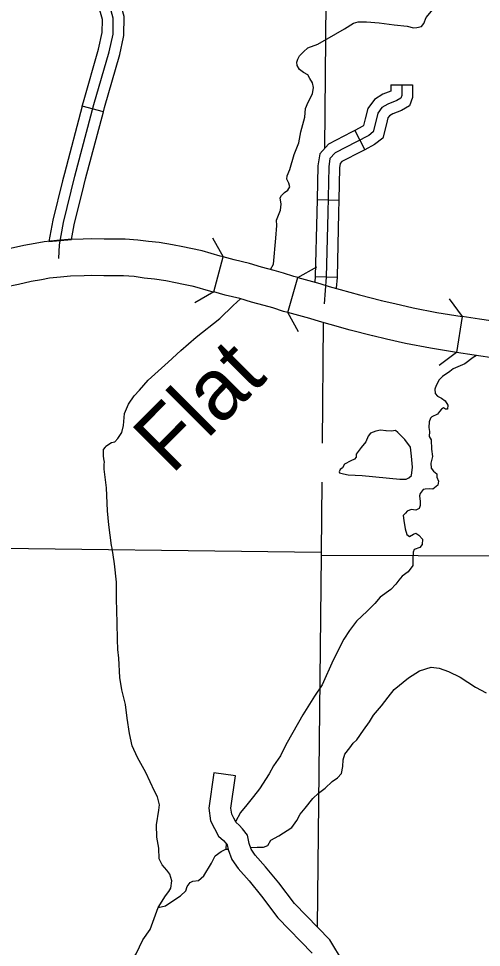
# Model space of a CAD drawing. Extents: x 813775 to 1157140, y 1757555 to 1979907.
# Drawn here: x 919245 to 925607, y 1817730 to 1830487 of the extents above; entities that cross this region are included whole.
import ezdxf

# ---------------------------------------------------------------- set-up
doc = ezdxf.new("R2010")
doc.units = 0
for name, color, linetype in [('Level 10', 7, 'Continuous'), ('Level 31', 7, 'Continuous'), ('Level 32', 7, 'Continuous'), ('Level 35', 7, 'Continuous'), ('Level 37', 7, 'Continuous'), ('Level 4', 7, 'Continuous'), ('Level 46', 7, 'Continuous'), ('Level 5', 7, 'Continuous')]:
    doc.layers.add(name, color=color, linetype=linetype)

msp = doc.modelspace()

# ---------------------------------------------------------------- linework, layer by layer
at = {"layer": 'Level 10'}
msp.add_line((922059, 1827214), (922059, 1827214), dxfattribs=at)
for points in [[(920131, 1827459), (919927, 1827452), (919773, 1827439), (919596, 1827420), (919472, 1827397), (919319, 1827371), (919136, 1827329), (918950, 1827290), (918743, 1827234), (918576, 1827192), (918447, 1827154), (918241, 1827102), (918071, 1827055)], [(921769, 1827296), (921614, 1827331), (921502, 1827353), (921360, 1827381), (921178, 1827411), (921029, 1827425), (920884, 1827444), (920710, 1827456), (920546, 1827459), (920420, 1827459), (920252, 1827462), (920133, 1827459)], [(922059, 1827214), (922017, 1827225), (921769, 1827296)], [(921928, 1826732), (922059, 1827214)], [(923026, 1826944), (922887, 1826990), (922757, 1827028), (922585, 1827074), (922417, 1827125), (922206, 1827175), (922059, 1827214)], [(918205, 1826573), (918369, 1826619), (918579, 1826671), (918708, 1826710), (918869, 1826750), (919067, 1826804), (919244, 1826841), (919416, 1826881), (919559, 1826905), (919668, 1826925), (919821, 1826941), (919957, 1826953), (920147, 1826959)], [(920145, 1826959), (920254, 1826962), (920415, 1826959), (920541, 1826959), (920689, 1826957), (920833, 1826947), (920972, 1826928), (921114, 1826914), (921271, 1826889), (921404, 1826863), (921511, 1826841), (921647, 1826811)], [(922946, 1826448), (923081, 1826929)], [(923081, 1826929), (923026, 1826944)], [(923081, 1826929), (923384, 1826847), (923516, 1826808), (923663, 1826768), (923931, 1826692), (924234, 1826614)], [(921632, 1826815), (921883, 1826743), (921928, 1826732)], [(922888, 1826464), (922739, 1826513), (922622, 1826546), (922448, 1826593), (922288, 1826641), (922083, 1826690), (921928, 1826732)], [(924229, 1826615), (924415, 1826572), (924667, 1826512), (924993, 1826451), (925340, 1826395)], [(922946, 1826448), (922888, 1826464)], [(924110, 1826130), (923801, 1826209), (923528, 1826286), (923379, 1826327), (923248, 1826366), (922946, 1826448)], [(925340, 1826395), (925266, 1825900)], [(926379, 1826241), (926083, 1826279), (925893, 1826312), (925581, 1826359), (925340, 1826395)], [(925266, 1825900), (924906, 1825959), (924564, 1826023), (924301, 1826085), (924115, 1826129)], [(926314, 1825745), (926009, 1825785), (925814, 1825818), (925507, 1825864), (925266, 1825900)]]:
    msp.add_lwpolyline(points, dxfattribs=at)
at = {"layer": 'Level 31'}
for p in [(920410, 1829207), (920120, 1829284)]:
    msp.add_line(p, (920120, 1829284), dxfattribs=at)
for points in [[(920393, 1830289), (920397, 1830474), (920331, 1830711), (920253, 1831083), (920229, 1831281), (920229, 1831294)], [(920688, 1830232), (920693, 1830253), (920698, 1830513), (920622, 1830783), (920549, 1831131), (920528, 1831306), (920528, 1831307)], [(920120, 1829284), (920136, 1829345), (920344, 1830068), (920395, 1830297)], [(920410, 1829207), (920426, 1829265), (920635, 1829994), (920688, 1830232)], [(920120, 1829284), (919874, 1828360), (919849, 1828260)], [(920141, 1828189), (920164, 1828286), (920410, 1829207)], [(919849, 1828260), (919717, 1827719), (919662, 1827427), (919972, 1827454)], [(919972, 1827454), (920010, 1827656), (920141, 1828189)]]:
    msp.add_lwpolyline(points, dxfattribs=at)
at = {"layer": 'Level 32'}
for p, q in [((924361, 1829579), (924661, 1829579)), ((923865, 1828951), (924005, 1828685)), ((923348, 1828000), (923648, 1827993)), ((923322, 1826945), (923622, 1826937))]:
    msp.add_line(p, q, dxfattribs=at)
for points in [[(919797, 1827190), (919806, 1827381), (919864, 1827688), (920019, 1828323), (920281, 1829305), (920490, 1830031), (920543, 1830271), (920547, 1830494), (920476, 1830747), (920401, 1831107), (920379, 1831294), (920370, 1831498), (920374, 1831694), (920454, 1832023), (920627, 1832397), (920938, 1832948), (921093, 1833299), (921187, 1833605), (921240, 1834010)], [(924361, 1829579), (924361, 1829490), (924253, 1829448), (924138, 1829377), (924044, 1829254), (924010, 1829109), (923987, 1829018), (923977, 1829010), (923865, 1828951)], [(924661, 1829579), (924661, 1829401), (924619, 1829290), (924510, 1829226), (924387, 1829178), (924342, 1829151), (924321, 1829123), (924302, 1829039), (924253, 1828843), (924139, 1828756), (924005, 1828685)], [(924511, 1829579), (924511, 1829428), (924498, 1829393), (924444, 1829362), (924320, 1829313), (924240, 1829264), (924182, 1829188)], [(924182, 1829188), (924156, 1829074), (924120, 1828931), (924058, 1828883), (923889, 1828794), (923596, 1828643), (923525, 1828563), (923508, 1828452), (923494, 1827821), (923472, 1826936), (923447, 1826568)], [(923865, 1828951), (923820, 1828927), (923503, 1828764), (923384, 1828630), (923358, 1828465), (923348, 1828000)], [(924005, 1828685), (923959, 1828661), (923690, 1828523), (923666, 1828496), (923657, 1828438), (923648, 1827993)], [(923348, 1828000), (923344, 1827824), (923322, 1826945)], [(923648, 1827993), (923644, 1827817), (923622, 1826937)], [(923322, 1826945), (923322, 1826943), (923317, 1826865)], [(923622, 1826937), (923622, 1826930), (923612, 1826782)]]:
    msp.add_lwpolyline(points, dxfattribs=at)
at = {"layer": 'Level 35'}
for points in [[(924200, 1830427), (924408, 1830401), (924585, 1830381), (924675, 1830358), (924721, 1830363), (924781, 1830376), (924817, 1830421), (924849, 1830502), (924922, 1830588), (925011, 1830686), (925053, 1830797), (925167, 1830908), (925293, 1830976), (925338, 1831042), (925366, 1831072), (925404, 1831085), (925447, 1831100), (925474, 1831135), (925484, 1831186), (925469, 1831213), (925457, 1831236), (925457, 1831266)], [(923224, 1829338), (923287, 1829451), (923297, 1829539), (923285, 1829605), (923249, 1829663), (923219, 1829713), (923161, 1829746), (923108, 1829789), (923075, 1829844), (923070, 1829890), (923081, 1829930), (923108, 1829973), (923159, 1830029), (923222, 1830084), (923358, 1830137), (923605, 1830276), (923723, 1830346), (923847, 1830425), (923912, 1830440), (924028, 1830442), (924200, 1830427)], [(922975, 1828414), (923033, 1828622), (923098, 1828778), (923126, 1828930), (923179, 1829134), (923189, 1829250), (923224, 1829338)], [(922707, 1827041), (922748, 1827115), (922779, 1827471), (922794, 1827647), (922789, 1827720), (922844, 1827854), (922854, 1827937), (922842, 1828023), (922859, 1828056), (922900, 1828096), (922945, 1828129), (922973, 1828175), (922960, 1828225), (922932, 1828280), (922935, 1828326), (922975, 1828414)], [(921027, 1825519), (921301, 1825769), (921475, 1825928), (921687, 1826110), (922010, 1826367), (922194, 1826547), (922295, 1826639)], [(925541, 1825859), (925494, 1825830), (925377, 1825743), (925217, 1825678), (925173, 1825640)], [(925173, 1825640), (925071, 1825571), (925028, 1825526)], [(920445, 1824616), (920521, 1824666), (920566, 1824676), (920609, 1824719), (920664, 1824800), (920687, 1824898), (920702, 1825062), (920755, 1825189), (920833, 1825305), (920909, 1825383), (921027, 1825519)], [(925028, 1825526), (924986, 1825448), (924965, 1825396), (924970, 1825339), (925003, 1825303), (925060, 1825274), (925109, 1825235), (925147, 1825176), (925139, 1825121), (925114, 1825121), (925084, 1825140), (925057, 1825124), (925030, 1825089), (925005, 1825053), (924924, 1825015), (924905, 1824999), (924889, 1824947), (924886, 1824871), (924894, 1824814), (924889, 1824749), (924916, 1824700), (924921, 1824572), (924932, 1824471), (924913, 1824379), (924916, 1824311), (924948, 1824270), (924992, 1824234), (924995, 1824188), (925016, 1824134), (925008, 1824079), (924940, 1824025), (924889, 1824030), (924834, 1824025), (924804, 1824020), (924766, 1823965), (924755, 1823930), (924766, 1823854), (924764, 1823799), (924750, 1823758), (924707, 1823737), (924639, 1823745), (924584, 1823720), (924563, 1823696), (924533, 1823663), (924541, 1823594)], [(924299, 1824827), (924220, 1824835), (924155, 1824821), (924084, 1824794), (924049, 1824750), (924016, 1824672), (923956, 1824595), (923886, 1824506), (923886, 1824465), (923861, 1824435), (923810, 1824413), (923725, 1824367), (923698, 1824315), (923663, 1824296), (923652, 1824263), (923658, 1824247), (923712, 1824236), (923774, 1824220), (923967, 1824212), (924484, 1824163), (924573, 1824163), (924611, 1824179), (924647, 1824212), (924658, 1824326), (924647, 1824476), (924630, 1824601), (924554, 1824704), (924457, 1824802), (924424, 1824829), (924372, 1824821), (924291, 1824827)], [(920523, 1823251), (920485, 1823535), (920468, 1823726), (920453, 1824042), (920420, 1824297), (920420, 1824365), (920425, 1824395), (920417, 1824440), (920412, 1824483), (920412, 1824526), (920412, 1824567), (920442, 1824602), (920445, 1824616)], [(924541, 1823594), (924557, 1823480)], [(924557, 1823480), (924582, 1823402), (924617, 1823374), (924671, 1823404), (924704, 1823418), (924747, 1823391), (924796, 1823336), (924793, 1823265), (924761, 1823222), (924682, 1823195), (924668, 1823157), (924663, 1823075), (924663, 1822974), (924601, 1822887), (924519, 1822828), (924470, 1822776), (924429, 1822721), (924361, 1822645), (924217, 1822539), (924141, 1822452), (924035, 1822349), (923888, 1822213), (923793, 1822082), (923717, 1821963)], [(920606, 1821959), (920601, 1822189), (920589, 1822517), (920591, 1822746), (920563, 1822996), (920533, 1823213), (920523, 1823251)], [(920768, 1820668), (920737, 1820877), (920715, 1821068), (920662, 1821270), (920639, 1821437), (920624, 1821702), (920611, 1821820), (920606, 1821959)], [(923717, 1821963), (923571, 1821674), (923416, 1821336), (923313, 1821181), (923150, 1820926), (923014, 1820681)], [(922435, 1819101), (922525, 1819106), (922612, 1819106), (922669, 1819131), (922710, 1819201), (922824, 1819264), (923001, 1819378), (923071, 1819473), (923115, 1819558), (923183, 1819642), (923289, 1819775), (923368, 1819849), (923460, 1819917), (923557, 1820008), (923628, 1820059), (923682, 1820119), (923701, 1820214), (923707, 1820307), (923729, 1820386), (923797, 1820473), (923846, 1820535), (923894, 1820579), (923984, 1820715), (924068, 1820829), (924123, 1820919), (924231, 1821049), (924327, 1821166), (924408, 1821274), (924604, 1821431), (924756, 1821529), (924914, 1821578), (925027, 1821565), (925155, 1821521), (925315, 1821442), (925525, 1821306), (925674, 1821227)], [(921113, 1819876), (920992, 1820131), (920879, 1820340), (920805, 1820499), (920768, 1820668)], [(923014, 1820681), (922917, 1820513), (922846, 1820363), (922751, 1820224), (922688, 1820113)], [(922688, 1820113), (922555, 1819910), (922474, 1819801), (922381, 1819687), (922294, 1819581), (922225, 1819455)], [(921164, 1818278), (921265, 1818438), (921308, 1818496), (921338, 1818544), (921350, 1818645), (921323, 1818736), (921285, 1818791), (921217, 1818862), (921176, 1818948), (921171, 1819094), (921144, 1819243), (921141, 1819412), (921171, 1819614), (921181, 1819687), (921169, 1819742), (921156, 1819798), (921113, 1819876)], [(922097, 1819159), (922093, 1819081)], [(921897, 1818885), (921947, 1818988), (922028, 1819049), (922093, 1819081)], [(922093, 1819081), (922124, 1819080)], [(921164, 1818278), (921265, 1818302), (921378, 1818380), (921469, 1818438), (921542, 1818509), (921562, 1818567), (921602, 1818620), (921638, 1818640), (921716, 1818647), (921791, 1818715), (921897, 1818885)], [(920630, 1817414), (920750, 1817480), (920861, 1817642), (920952, 1817834), (921053, 1817975), (921164, 1818278)]]:
    msp.add_lwpolyline(points, dxfattribs=at)
at = {"layer": 'Level 37'}
for points in [[(921910, 1827474), (922059, 1827214)], [(923081, 1826929), (923343, 1827076)], [(921928, 1826732), (921668, 1826582)], [(925161, 1826636), (925340, 1826395)], [(923092, 1826186), (922945, 1826448)], [(925266, 1825900), (925025, 1825722)]]:
    msp.add_lwpolyline(points, dxfattribs=at)
at = {"layer": 'Level 4'}
for points in [[(923506, 1834683), (923497, 1833778), (923497, 1833742), (923452, 1828706)], [(923430, 1826313), (923416, 1824657)], [(923411, 1824121), (923402, 1823158), (923402, 1823119), (923349, 1818012)]]:
    msp.add_lwpolyline(points, dxfattribs=at)
at = {"layer": 'Level 46'}
for points in [[(922228, 1820087), (921931, 1820130), (921861, 1819642), (921885, 1819468), (921938, 1819363), (921995, 1819259), (922061, 1819198), (922095, 1819161), (922113, 1819140), (922125, 1819077), (922175, 1818939), (922262, 1818813), (922413, 1818645), (922586, 1818432), (922808, 1818137), (923282, 1817651)], [(923521, 1817836), (923036, 1818333), (922823, 1818617), (922641, 1818839), (922498, 1818999), (922444, 1819078), (922415, 1819158), (922392, 1819273), (922322, 1819358), (922275, 1819410), (922234, 1819447), (922203, 1819503), (922176, 1819558), (922164, 1819641), (922228, 1820087)], [(924755, 1816056), (924564, 1816084), (924560, 1816085), (924547, 1816099), (924462, 1816314), (924423, 1816580), (924348, 1816676), (924253, 1816791), (924087, 1816947), (924019, 1817026), (923926, 1817205), (923710, 1817525), (923521, 1817836)]]:
    msp.add_lwpolyline(points, dxfattribs=at)
at = {"layer": 'Level 5'}
for points in [[(918281, 1823224), (923402, 1823158)], [(923402, 1823119), (927410, 1823105), (931589, 1823121)]]:
    msp.add_lwpolyline(points, dxfattribs=at)

# ---------------------------------------------------------------- texts
at = {"layer": 'Level 35'}
msp.add_text('Flat', height=844.8, rotation=45.0283, dxfattribs=at).set_placement((921349, 1824213))

doc.saveas('drawing.dxf')
